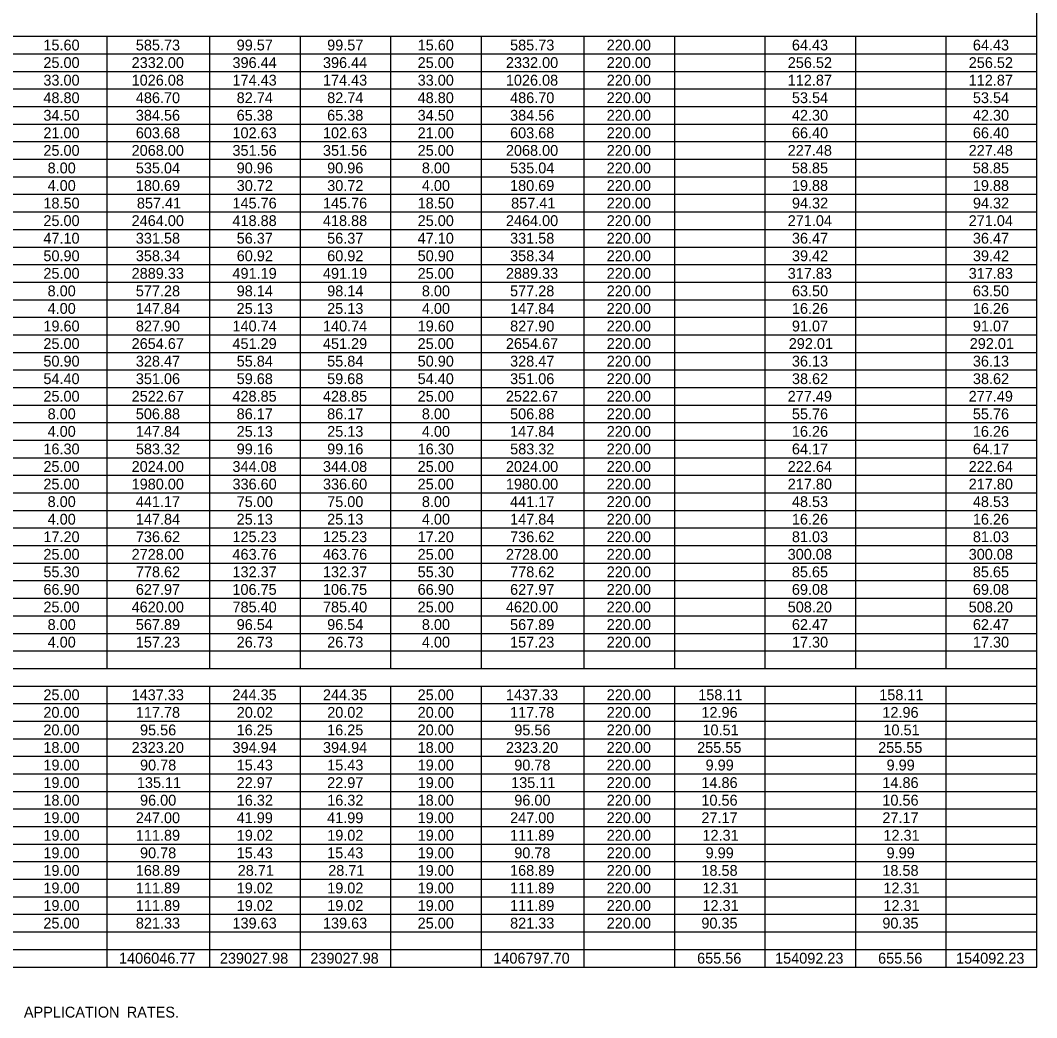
# Model space of a CAD drawing. Extents: x 2261867 to 2275370, y -3124789 to -3122260.
# Drawn here: x 2269943 to 2270507, y -3123462 to -3122908 of the extents above; entities that cross this region are included whole.
import ezdxf

# ---------------------------------------------------------------- set-up
doc = ezdxf.new("R2010")
doc.units = 0
doc.layers.add('Default', color=7, linetype='Continuous')

msp = doc.modelspace()

# ---------------------------------------------------------------- linework, layer by layer
at = {"layer": 'Default'}
for p, q in [((2270507.08, -3123434.1), (2270507.08, -3122273.85)), ((2269380.47, -3122917.35), (2270507.08, -3122917.35)), ((2269991.31, -3123268.35), (2269991.31, -3122917.35)), ((2269991.31, -3123268.35), (2269991.31, -3122917.35)), ((2270048.34, -3123268.35), (2270048.34, -3122917.35)), ((2270048.34, -3123268.35), (2270048.34, -3122917.35)), ((2270098.56, -3123268.35), (2270098.56, -3122917.35)), ((2270098.56, -3123268.35), (2270098.56, -3122917.35)), ((2270148.77, -3123268.35), (2270148.77, -3122917.35)), ((2270148.77, -3123268.35), (2270148.77, -3122917.35)), ((2270198.98, -3123268.35), (2270198.98, -3122917.35)), ((2270198.98, -3123268.35), (2270198.98, -3122917.35)), ((2270256.02, -3123268.35), (2270256.02, -3122917.35)), ((2270256.02, -3123268.35), (2270256.02, -3122917.35)), ((2270306.23, -3123268.35), (2270306.23, -3122917.35)), ((2270306.23, -3123268.35), (2270306.23, -3122917.35)), ((2270356.44, -3123268.35), (2270356.44, -3122917.35)), ((2270356.44, -3123268.35), (2270356.44, -3122917.35)), ((2270406.66, -3123268.35), (2270406.66, -3122917.35)), ((2270406.66, -3123268.35), (2270406.66, -3122917.35)), ((2270456.87, -3123268.35), (2270456.87, -3122917.35)), ((2270456.87, -3123268.35), (2270456.87, -3122917.35)), ((2270507.08, -3123268.35), (2270507.08, -3122917.35)), ((2269380.47, -3122927.1), (2270507.08, -3122927.1)), ((2269380.47, -3122936.85), (2270507.08, -3122936.85)), ((2269380.47, -3122946.6), (2270507.08, -3122946.6)), ((2269380.47, -3122956.35), (2270507.08, -3122956.35)), ((2269380.47, -3122966.1), (2270507.08, -3122966.1)), ((2269380.47, -3122975.85), (2270507.08, -3122975.85)), ((2269380.47, -3122985.6), (2270507.08, -3122985.6)), ((2269380.47, -3122995.35), (2270507.08, -3122995.35)), ((2269380.47, -3123005.1), (2270507.08, -3123005.1)), ((2269380.47, -3123014.85), (2270507.08, -3123014.85)), ((2269380.47, -3123024.6), (2270507.08, -3123024.6)), ((2269380.47, -3123034.35), (2270507.08, -3123034.35)), ((2269380.47, -3123044.1), (2270507.08, -3123044.1)), ((2269380.47, -3123053.85), (2270507.08, -3123053.85)), ((2269380.47, -3123063.6), (2270507.08, -3123063.6)), ((2269380.47, -3123073.35), (2270507.08, -3123073.35)), ((2269380.47, -3123083.1), (2270507.08, -3123083.1)), ((2269380.47, -3123092.85), (2270507.08, -3123092.85)), ((2269380.47, -3123102.6), (2270507.08, -3123102.6)), ((2269380.47, -3123112.35), (2270507.08, -3123112.35)), ((2269380.47, -3123122.1), (2270507.08, -3123122.1)), ((2269380.47, -3123131.85), (2270507.08, -3123131.85)), ((2269380.47, -3123141.6), (2270507.08, -3123141.6)), ((2269380.47, -3123151.35), (2270507.08, -3123151.35)), ((2269380.47, -3123161.1), (2270507.08, -3123161.1)), ((2269380.47, -3123170.85), (2270507.08, -3123170.85)), ((2269380.47, -3123180.6), (2270507.08, -3123180.6)), ((2269380.47, -3123190.35), (2270507.08, -3123190.35)), ((2269380.47, -3123200.1), (2270507.08, -3123200.1)), ((2269380.47, -3123209.85), (2270507.08, -3123209.85)), ((2269380.47, -3123219.6), (2270507.08, -3123219.6)), ((2269380.47, -3123229.35), (2270507.08, -3123229.35)), ((2269380.47, -3123239.1), (2270507.08, -3123239.1)), ((2269380.47, -3123248.85), (2270507.08, -3123248.85)), ((2269380.47, -3123258.6), (2270507.08, -3123258.6)), ((2269380.47, -3123268.35), (2270507.08, -3123268.35)), ((2269380.47, -3123268.35), (2270507.08, -3123268.35)), ((2269380.47, -3123278.1), (2270507.08, -3123278.1)), ((2269991.31, -3123434.1), (2269991.31, -3123278.1)), ((2269991.31, -3123434.1), (2269991.31, -3123278.1)), ((2270048.34, -3123414.6), (2270048.34, -3123278.1)), ((2270048.34, -3123434.1), (2270048.34, -3123278.1)), ((2270098.56, -3123414.6), (2270098.56, -3123278.1)), ((2270098.56, -3123434.1), (2270098.56, -3123278.1)), ((2270148.77, -3123424.35), (2270148.77, -3123278.1)), ((2270148.77, -3123434.1), (2270148.77, -3123278.1)), ((2270198.98, -3123434.1), (2270198.98, -3123278.1)), ((2270198.98, -3123434.1), (2270198.98, -3123278.1)), ((2270256.02, -3123434.1), (2270256.02, -3123278.1)), ((2270256.02, -3123434.1), (2270256.02, -3123278.1)), ((2270306.23, -3123434.1), (2270306.23, -3123278.1)), ((2270306.23, -3123434.1), (2270306.23, -3123278.1)), ((2270356.44, -3123424.35), (2270356.44, -3123278.1)), ((2270356.44, -3123434.1), (2270356.44, -3123278.1)), ((2270406.66, -3123424.35), (2270406.66, -3123278.1)), ((2270406.66, -3123434.1), (2270406.66, -3123278.1)), ((2270456.87, -3123424.35), (2270456.87, -3123278.1)), ((2270456.87, -3123434.1), (2270456.87, -3123278.1)), ((2270507.08, -3123424.35), (2270507.08, -3123278.1)), ((2269380.47, -3123287.85), (2270507.08, -3123287.85)), ((2269380.47, -3123297.6), (2270507.08, -3123297.6)), ((2269380.47, -3123307.35), (2270507.08, -3123307.35)), ((2269380.47, -3123317.1), (2270507.08, -3123317.1)), ((2269380.47, -3123326.85), (2270507.08, -3123326.85)), ((2269380.47, -3123336.6), (2270507.08, -3123336.6)), ((2269380.47, -3123346.35), (2270507.08, -3123346.35)), ((2269380.47, -3123356.1), (2270507.08, -3123356.1)), ((2269380.47, -3123365.85), (2270507.08, -3123365.85)), ((2269380.47, -3123375.6), (2270507.08, -3123375.6)), ((2269380.47, -3123385.35), (2270507.08, -3123385.35)), ((2269380.47, -3123395.1), (2270507.08, -3123395.1)), ((2269380.47, -3123404.85), (2270507.08, -3123404.85)), ((2269380.47, -3123414.6), (2270507.08, -3123414.6)), ((2269380.47, -3123424.35), (2270507.08, -3123424.35)), ((2269941.09, -3123424.35), (2269991.31, -3123424.35)), ((2269991.31, -3123424.35), (2270098.56, -3123424.35)), ((2270098.56, -3123424.35), (2270507.08, -3123424.35)), ((2269380.47, -3123434.1), (2270507.08, -3123434.1))]:
    msp.add_line(p, q, dxfattribs=at)

# ---------------------------------------------------------------- texts
for s, p in [('15.60', (2269955.92, -3122925.22)), ('585.73', (2270007.2, -3122925.22)), ('99.57', (2270063.16, -3122925.22)), ('99.57', (2270113.37, -3122925.22)), ('15.60', (2270163.59, -3122925.22)), ('585.73', (2270214.88, -3122925.22)), ('220.00', (2270268.51, -3122925.22)), ('64.43', (2270371.26, -3122925.22)), ('64.43', (2270471.68, -3122925.22)), ('25.00', (2269955.92, -3122934.97)), ('2332.00', (2270004.88, -3122934.97)), ('396.44', (2270060.84, -3122934.97)), ('396.44', (2270111.05, -3122934.97)), ('25.00', (2270163.59, -3122934.97)), ('2332.00', (2270212.56, -3122934.97)), ('220.00', (2270268.51, -3122934.97)), ('256.52', (2270368.96, -3122934.97)), ('256.52', (2270469.38, -3122934.97)), ('33.00', (2269955.92, -3122944.72)), ('1026.08', (2270004.87, -3122944.72)), ('174.43', (2270060.83, -3122944.72)), ('174.43', (2270111.04, -3122944.72)), ('33.00', (2270163.59, -3122944.72)), ('1026.08', (2270212.54, -3122944.72)), ('220.00', (2270268.51, -3122944.72)), ('112.87', (2270368.93, -3122944.72)), ('112.87', (2270469.35, -3122944.72)), ('48.80', (2269955.92, -3122954.47)), ('486.70', (2270007.21, -3122954.47)), ('82.74', (2270063.17, -3122954.47)), ('82.74', (2270113.38, -3122954.47)), ('48.80', (2270163.59, -3122954.47)), ('486.70', (2270214.89, -3122954.47)), ('220.00', (2270268.51, -3122954.47)), ('53.54', (2270371.27, -3122954.47)), ('53.54', (2270471.69, -3122954.47)), ('34.50', (2269955.92, -3122964.22)), ('384.56', (2270007.2, -3122964.22)), ('65.38', (2270063.15, -3122964.22)), ('65.38', (2270113.36, -3122964.22)), ('34.50', (2270163.59, -3122964.22)), ('384.56', (2270214.88, -3122964.22)), ('220.00', (2270268.51, -3122964.22)), ('42.30', (2270371.27, -3122964.22)), ('42.30', (2270471.69, -3122964.22)), ('21.00', (2269955.92, -3122973.97)), ('603.68', (2270007.2, -3122973.97)), ('102.63', (2270060.83, -3122973.97)), ('102.63', (2270111.04, -3122973.97)), ('21.00', (2270163.59, -3122973.97)), ('603.68', (2270214.87, -3122973.97)), ('220.00', (2270268.51, -3122973.97)), ('66.40', (2270371.27, -3122973.97)), ('66.40', (2270471.69, -3122973.97)), ('25.00', (2269955.92, -3122983.72)), ('2068.00', (2270004.88, -3122983.72)), ('351.56', (2270060.83, -3122983.72)), ('351.56', (2270111.04, -3122983.72)), ('25.00', (2270163.59, -3122983.72)), ('2068.00', (2270212.56, -3122983.72)), ('220.00', (2270268.51, -3122983.72)), ('227.48', (2270368.92, -3122983.72)), ('227.48', (2270469.35, -3122983.72)), ('8.00', (2269958.25, -3122993.47)), ('535.04', (2270007.21, -3122993.47)), ('90.96', (2270063.16, -3122993.47)), ('90.96', (2270113.37, -3122993.47)), ('8.00', (2270165.92, -3122993.47)), ('535.04', (2270214.89, -3122993.47)), ('220.00', (2270268.51, -3122993.47)), ('58.85', (2270371.23, -3122993.47)), ('58.85', (2270471.66, -3122993.47)), ('4.00', (2269958.25, -3123003.22)), ('180.69', (2270007.2, -3123003.22)), ('30.72', (2270063.19, -3123003.22)), ('30.72', (2270113.4, -3123003.22)), ('4.00', (2270165.92, -3123003.22)), ('180.69', (2270214.87, -3123003.22)), ('220.00', (2270268.51, -3123003.22)), ('19.88', (2270371.25, -3123003.22)), ('19.88', (2270471.68, -3123003.22)), ('18.50', (2269955.92, -3123012.97)), ('857.41', (2270007.78, -3123012.97)), ('145.76', (2270060.83, -3123012.97)), ('145.76', (2270111.04, -3123012.97)), ('18.50', (2270163.59, -3123012.97)), ('857.41', (2270215.46, -3123012.97)), ('220.00', (2270268.51, -3123012.97)), ('94.32', (2270371.29, -3123012.97)), ('94.32', (2270471.71, -3123012.97)), ('25.00', (2269955.92, -3123022.72)), ('2464.00', (2270004.88, -3123022.72)), ('418.88', (2270060.82, -3123022.72)), ('418.88', (2270111.03, -3123022.72)), ('25.00', (2270163.59, -3123022.72)), ('2464.00', (2270212.56, -3123022.72)), ('220.00', (2270268.51, -3123022.72)), ('271.04', (2270368.94, -3123022.72)), ('271.04', (2270469.36, -3123022.72)), ('47.10', (2269955.92, -3123032.47)), ('331.58', (2270007.2, -3123032.47)), ('56.37', (2270063.16, -3123032.47)), ('56.37', (2270113.37, -3123032.47)), ('47.10', (2270163.59, -3123032.47)), ('331.58', (2270214.87, -3123032.47)), ('220.00', (2270268.51, -3123032.47)), ('36.47', (2270371.26, -3123032.47)), ('36.47', (2270471.68, -3123032.47)), ('50.90', (2269955.92, -3123042.22)), ('358.34', (2270007.21, -3123042.22)), ('60.92', (2270063.19, -3123042.22)), ('60.92', (2270113.4, -3123042.22)), ('50.90', (2270163.59, -3123042.22)), ('358.34', (2270214.89, -3123042.22)), ('220.00', (2270268.51, -3123042.22)), ('39.42', (2270371.29, -3123042.22)), ('39.42', (2270471.71, -3123042.22)), ('25.00', (2269955.92, -3123051.97)), ('2889.33', (2270004.87, -3123051.97)), ('491.19', (2270060.82, -3123051.97)), ('491.19', (2270111.03, -3123051.97)), ('25.00', (2270163.59, -3123051.97)), ('2889.33', (2270212.55, -3123051.97)), ('220.00', (2270268.51, -3123051.97)), ('317.83', (2270368.93, -3123051.97)), ('317.83', (2270469.35, -3123051.97)), ('8.00', (2269958.25, -3123061.72)), ('577.28', (2270007.2, -3123061.72)), ('98.14', (2270063.17, -3123061.72)), ('98.14', (2270113.38, -3123061.72)), ('8.00', (2270165.92, -3123061.72)), ('577.28', (2270214.87, -3123061.72)), ('220.00', (2270268.51, -3123061.72)), ('63.50', (2270371.27, -3123061.72)), ('63.50', (2270471.69, -3123061.72)), ('4.00', (2269958.25, -3123071.47)), ('147.84', (2270007.21, -3123071.47)), ('25.13', (2270063.16, -3123071.47)), ('25.13', (2270113.37, -3123071.47)), ('4.00', (2270165.92, -3123071.47)), ('147.84', (2270214.89, -3123071.47)), ('220.00', (2270268.51, -3123071.47)), ('16.26', (2270371.26, -3123071.47)), ('16.26', (2270471.68, -3123071.47)), ('19.60', (2269955.92, -3123081.22)), ('827.90', (2270007.21, -3123081.22)), ('140.74', (2270060.84, -3123081.22)), ('140.74', (2270111.05, -3123081.22)), ('19.60', (2270163.59, -3123081.22)), ('827.90', (2270214.89, -3123081.22)), ('220.00', (2270268.51, -3123081.22)), ('91.07', (2270371.26, -3123081.22)), ('91.07', (2270471.68, -3123081.22)), ('25.00', (2269955.92, -3123090.97)), ('2654.67', (2270004.87, -3123090.97)), ('451.29', (2270060.82, -3123090.97)), ('451.29', (2270111.03, -3123090.97)), ('25.00', (2270163.59, -3123090.97)), ('2654.67', (2270212.55, -3123090.97)), ('220.00', (2270268.51, -3123090.97)), ('292.01', (2270369.51, -3123090.97)), ('292.01', (2270469.93, -3123090.97)), ('50.90', (2269955.92, -3123100.72)), ('328.47', (2270007.2, -3123100.72)), ('55.84', (2270063.17, -3123100.72)), ('55.84', (2270113.38, -3123100.72)), ('50.90', (2270163.59, -3123100.72)), ('328.47', (2270214.88, -3123100.72)), ('220.00', (2270268.51, -3123100.72)), ('36.13', (2270371.26, -3123100.72)), ('36.13', (2270471.68, -3123100.72)), ('54.40', (2269955.92, -3123110.47)), ('351.06', (2270007.2, -3123110.47)), ('59.68', (2270063.15, -3123110.47)), ('59.68', (2270113.36, -3123110.47)), ('54.40', (2270163.59, -3123110.47)), ('351.06', (2270214.88, -3123110.47)), ('220.00', (2270268.51, -3123110.47)), ('38.62', (2270371.29, -3123110.47)), ('38.62', (2270471.71, -3123110.47)), ('25.00', (2269955.92, -3123120.22)), ('2522.67', (2270004.87, -3123120.22)), ('428.85', (2270060.8, -3123120.22)), ('428.85', (2270111.02, -3123120.22)), ('25.00', (2270163.59, -3123120.22)), ('2522.67', (2270212.55, -3123120.22)), ('220.00', (2270268.51, -3123120.22)), ('277.49', (2270368.92, -3123120.22)), ('277.49', (2270469.35, -3123120.22)), ('8.00', (2269958.25, -3123129.97)), ('506.88', (2270007.2, -3123129.97)), ('86.17', (2270063.16, -3123129.97)), ('86.17', (2270113.37, -3123129.97)), ('8.00', (2270165.92, -3123129.97)), ('506.88', (2270214.87, -3123129.97)), ('220.00', (2270268.51, -3123129.97)), ('55.76', (2270371.26, -3123129.97)), ('55.76', (2270471.68, -3123129.97)), ('4.00', (2269958.25, -3123139.72)), ('147.84', (2270007.21, -3123139.72)), ('25.13', (2270063.16, -3123139.72)), ('25.13', (2270113.37, -3123139.72)), ('4.00', (2270165.92, -3123139.72)), ('147.84', (2270214.89, -3123139.72)), ('220.00', (2270268.51, -3123139.72)), ('16.26', (2270371.26, -3123139.72)), ('16.26', (2270471.68, -3123139.72)), ('16.30', (2269955.92, -3123149.47)), ('583.32', (2270007.23, -3123149.47)), ('99.16', (2270063.16, -3123149.47)), ('99.16', (2270113.37, -3123149.47)), ('16.30', (2270163.59, -3123149.47)), ('583.32', (2270214.91, -3123149.47)), ('220.00', (2270268.51, -3123149.47)), ('64.17', (2270371.26, -3123149.47)), ('64.17', (2270471.68, -3123149.47)), ('25.00', (2269955.92, -3123159.22)), ('2024.00', (2270004.88, -3123159.22)), ('344.08', (2270060.82, -3123159.22)), ('344.08', (2270111.03, -3123159.22)), ('25.00', (2270163.59, -3123159.22)), ('2024.00', (2270212.56, -3123159.22)), ('220.00', (2270268.51, -3123159.22)), ('222.64', (2270368.94, -3123159.22)), ('222.64', (2270469.36, -3123159.22)), ('25.00', (2269955.92, -3123168.97)), ('1980.00', (2270004.88, -3123168.97)), ('336.60', (2270060.84, -3123168.97)), ('336.60', (2270111.05, -3123168.97)), ('25.00', (2270163.59, -3123168.97)), ('1980.00', (2270212.56, -3123168.97)), ('220.00', (2270268.51, -3123168.97)), ('217.80', (2270368.94, -3123168.97)), ('217.80', (2270469.36, -3123168.97)), ('8.00', (2269958.25, -3123178.72)), ('441.17', (2270007.2, -3123178.72)), ('75.00', (2270063.17, -3123178.72)), ('75.00', (2270113.38, -3123178.72)), ('8.00', (2270165.92, -3123178.72)), ('441.17', (2270214.88, -3123178.72)), ('220.00', (2270268.51, -3123178.72)), ('48.53', (2270371.26, -3123178.72)), ('48.53', (2270471.68, -3123178.72)), ('4.00', (2269958.25, -3123188.47)), ('147.84', (2270007.21, -3123188.47)), ('25.13', (2270063.16, -3123188.47)), ('25.13', (2270113.37, -3123188.47)), ('4.00', (2270165.92, -3123188.47)), ('147.84', (2270214.89, -3123188.47)), ('220.00', (2270268.51, -3123188.47)), ('16.26', (2270371.26, -3123188.47)), ('16.26', (2270471.68, -3123188.47)), ('17.20', (2269955.92, -3123198.22)), ('736.62', (2270007.23, -3123198.22)), ('125.23', (2270060.83, -3123198.22)), ('125.23', (2270111.04, -3123198.22)), ('17.20', (2270163.59, -3123198.22)), ('736.62', (2270214.91, -3123198.22)), ('220.00', (2270268.51, -3123198.22)), ('81.03', (2270371.26, -3123198.22)), ('81.03', (2270471.68, -3123198.22)), ('25.00', (2269955.92, -3123207.97)), ('2728.00', (2270004.88, -3123207.97)), ('463.76', (2270060.83, -3123207.97)), ('463.76', (2270111.04, -3123207.97)), ('25.00', (2270163.59, -3123207.97)), ('2728.00', (2270212.56, -3123207.97)), ('220.00', (2270268.51, -3123207.97)), ('300.08', (2270368.92, -3123207.97)), ('300.08', (2270469.35, -3123207.97)), ('55.30', (2269955.92, -3123217.72)), ('778.62', (2270007.23, -3123217.72)), ('132.37', (2270060.83, -3123217.72)), ('132.37', (2270111.04, -3123217.72)), ('55.30', (2270163.59, -3123217.72)), ('778.62', (2270214.91, -3123217.72)), ('220.00', (2270268.51, -3123217.72)), ('85.65', (2270371.23, -3123217.72)), ('85.65', (2270471.66, -3123217.72)), ('66.90', (2269955.92, -3123227.47)), ('627.97', (2270007.2, -3123227.47)), ('106.75', (2270060.8, -3123227.47)), ('106.75', (2270111.02, -3123227.47)), ('66.90', (2270163.59, -3123227.47)), ('627.97', (2270214.88, -3123227.47)), ('220.00', (2270268.51, -3123227.47)), ('69.08', (2270371.25, -3123227.47)), ('69.08', (2270471.68, -3123227.47)), ('25.00', (2269955.92, -3123237.22)), ('4620.00', (2270004.88, -3123237.22)), ('785.40', (2270060.84, -3123237.22)), ('785.40', (2270111.05, -3123237.22)), ('25.00', (2270163.59, -3123237.22)), ('4620.00', (2270212.56, -3123237.22)), ('220.00', (2270268.51, -3123237.22)), ('508.20', (2270368.94, -3123237.22)), ('508.20', (2270469.36, -3123237.22)), ('8.00', (2269958.25, -3123246.97)), ('567.89', (2270007.2, -3123246.97)), ('96.54', (2270063.17, -3123246.97)), ('96.54', (2270113.38, -3123246.97)), ('8.00', (2270165.92, -3123246.97)), ('567.89', (2270214.87, -3123246.97)), ('220.00', (2270268.51, -3123246.97)), ('62.47', (2270371.26, -3123246.97)), ('62.47', (2270471.68, -3123246.97)), ('4.00', (2269958.25, -3123256.72)), ('157.23', (2270007.2, -3123256.72)), ('26.73', (2270063.16, -3123256.72)), ('26.73', (2270113.37, -3123256.72)), ('4.00', (2270165.92, -3123256.72)), ('157.23', (2270214.88, -3123256.72)), ('220.00', (2270268.51, -3123256.72)), ('17.30', (2270371.27, -3123256.72)), ('17.30', (2270471.69, -3123256.72)), ('25.00', (2269955.92, -3123285.97)), ('1437.33', (2270004.87, -3123285.97)), ('244.35', (2270060.8, -3123285.97)), ('244.35', (2270111.02, -3123285.97)), ('25.00', (2270163.59, -3123285.97)), ('1437.33', (2270212.55, -3123285.97)), ('220.00', (2270268.51, -3123285.97)), ('158.11', (2270319.29, -3123285.97)), ('158.11', (2270419.72, -3123285.97)), ('20.00', (2269955.92, -3123295.72)), ('117.78', (2270007.2, -3123295.72)), ('20.02', (2270063.19, -3123295.72)), ('20.02', (2270113.4, -3123295.72)), ('20.00', (2270163.59, -3123295.72)), ('117.78', (2270214.87, -3123295.72)), ('220.00', (2270268.51, -3123295.72)), ('12.96', (2270321.04, -3123295.72)), ('12.96', (2270421.47, -3123295.72)), ('20.00', (2269955.92, -3123305.47)), ('95.56', (2270009.53, -3123305.47)), ('16.25', (2270063.13, -3123305.47)), ('16.25', (2270113.35, -3123305.47)), ('20.00', (2270163.59, -3123305.47)), ('95.56', (2270217.21, -3123305.47)), ('220.00', (2270268.51, -3123305.47)), ('10.51', (2270321.62, -3123305.47)), ('10.51', (2270422.05, -3123305.47)), ('18.00', (2269955.92, -3123315.22)), ('2323.20', (2270004.88, -3123315.22)), ('394.94', (2270060.84, -3123315.22)), ('394.94', (2270111.05, -3123315.22)), ('18.00', (2270163.59, -3123315.22)), ('2323.20', (2270212.56, -3123315.22)), ('220.00', (2270268.51, -3123315.22)), ('255.55', (2270318.69, -3123315.22)), ('255.55', (2270419.12, -3123315.22)), ('19.00', (2269955.92, -3123324.97)), ('90.78', (2270009.53, -3123324.97)), ('15.43', (2270063.16, -3123324.97)), ('15.43', (2270113.37, -3123324.97)), ('19.00', (2270163.59, -3123324.97)), ('90.78', (2270217.2, -3123324.97)), ('220.00', (2270268.51, -3123324.97)), ('9.99', (2270323.37, -3123324.97)), ('9.99', (2270423.79, -3123324.97)), ('19.00', (2269955.92, -3123334.72)), ('135.11', (2270007.78, -3123334.72)), ('22.97', (2270063.16, -3123334.72)), ('22.97', (2270113.37, -3123334.72)), ('19.00', (2270163.59, -3123334.72)), ('135.11', (2270215.46, -3123334.72)), ('220.00', (2270268.51, -3123334.72)), ('14.86', (2270321.04, -3123334.72)), ('14.86', (2270421.47, -3123334.72)), ('18.00', (2269955.92, -3123344.47)), ('96.00', (2270009.54, -3123344.47)), ('16.32', (2270063.19, -3123344.47)), ('16.32', (2270113.4, -3123344.47)), ('18.00', (2270163.59, -3123344.47)), ('96.00', (2270217.22, -3123344.47)), ('220.00', (2270268.51, -3123344.47)), ('10.56', (2270321.04, -3123344.47)), ('10.56', (2270421.47, -3123344.47)), ('19.00', (2269955.92, -3123354.22)), ('247.00', (2270007.21, -3123354.22)), ('41.99', (2270063.15, -3123354.22)), ('41.99', (2270113.36, -3123354.22)), ('19.00', (2270163.59, -3123354.22)), ('247.00', (2270214.89, -3123354.22)), ('220.00', (2270268.51, -3123354.22)), ('27.17', (2270321.04, -3123354.22)), ('27.17', (2270421.47, -3123354.22)), ('19.00', (2269955.92, -3123363.97)), ('111.89', (2270007.2, -3123363.97)), ('19.02', (2270063.19, -3123363.97)), ('19.02', (2270113.4, -3123363.97)), ('19.00', (2270163.59, -3123363.97)), ('111.89', (2270214.87, -3123363.97)), ('220.00', (2270268.51, -3123363.97)), ('12.31', (2270321.62, -3123363.97)), ('12.31', (2270422.05, -3123363.97)), ('19.00', (2269955.92, -3123373.72)), ('90.78', (2270009.53, -3123373.72)), ('15.43', (2270063.16, -3123373.72)), ('15.43', (2270113.37, -3123373.72)), ('19.00', (2270163.59, -3123373.72)), ('90.78', (2270217.2, -3123373.72)), ('220.00', (2270268.51, -3123373.72)), ('9.99', (2270323.37, -3123373.72)), ('9.99', (2270423.79, -3123373.72)), ('19.00', (2269955.92, -3123383.47)), ('168.89', (2270007.2, -3123383.47)), ('28.71', (2270063.74, -3123383.47)), ('28.71', (2270113.95, -3123383.47)), ('19.00', (2270163.59, -3123383.47)), ('168.89', (2270214.87, -3123383.47)), ('220.00', (2270268.51, -3123383.47)), ('18.58', (2270321.04, -3123383.47)), ('18.58', (2270421.46, -3123383.47)), ('19.00', (2269955.92, -3123393.22)), ('111.89', (2270007.2, -3123393.22)), ('19.02', (2270063.19, -3123393.22)), ('19.02', (2270113.4, -3123393.22)), ('19.00', (2270163.59, -3123393.22)), ('111.89', (2270214.87, -3123393.22)), ('220.00', (2270268.51, -3123393.22)), ('12.31', (2270321.62, -3123393.22)), ('12.31', (2270422.05, -3123393.22)), ('19.00', (2269955.92, -3123402.97)), ('111.89', (2270007.2, -3123402.97)), ('19.02', (2270063.19, -3123402.97)), ('19.02', (2270113.4, -3123402.97)), ('19.00', (2270163.59, -3123402.97)), ('111.89', (2270214.87, -3123402.97)), ('220.00', (2270268.51, -3123402.97)), ('12.31', (2270321.62, -3123402.97)), ('12.31', (2270422.05, -3123402.97)), ('25.00', (2269955.92, -3123412.72)), ('821.33', (2270007.2, -3123412.72)), ('139.63', (2270060.83, -3123412.72)), ('139.63', (2270111.04, -3123412.72)), ('25.00', (2270163.59, -3123412.72)), ('821.33', (2270214.88, -3123412.72)), ('220.00', (2270268.51, -3123412.72)), ('90.35', (2270321.02, -3123412.72)), ('90.35', (2270421.45, -3123412.72)), ('1406046.77', (2269997.88, -3123432.22)), ('239027.98', (2270053.83, -3123432.22)), ('239027.98', (2270104.05, -3123432.22)), ('1406797.70', (2270205.57, -3123432.22)), ('655.56', (2270318.67, -3123432.22)), ('154092.23', (2270361.93, -3123432.22)), ('655.56', (2270419.1, -3123432.22)), ('154092.23', (2270462.35, -3123432.22)), (' APPLICATION', (2269942.86, -3123462.15)), (' RATES.', (2269999.95, -3123462.15))]:
    msp.add_text(s, height=6, dxfattribs=at).set_placement(p)

doc.saveas('drawing.dxf')
